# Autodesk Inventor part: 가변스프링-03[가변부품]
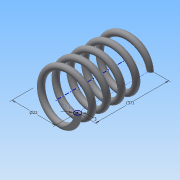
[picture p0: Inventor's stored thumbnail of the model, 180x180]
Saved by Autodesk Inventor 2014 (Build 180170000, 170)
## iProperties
Created: 2015-09
Part Number: 가변스프링-03[가변부품]
Material: 강철, 탄소
Document SubType Name: Modeling
Designer: study
Density: 7.87 g/cm^3
Appearance: 반연마
Mass: 18.8856 g
Surface Area: 32.5491 cm^2
Volume: 2.3997 cm^3
Author: study
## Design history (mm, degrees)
sketch "스케치1"
  geometry: L1 (0, 0)-(11, 0); L2 (11, 0)-(11, 36.411); L3 (11, 36.411)-(0, 36.411); L4 (0, 36.411)-(0, 0); C1 r 1.5 at (11, 0)
  constraints: 8 end point, 2 parallel, 1 centre point, 1 coincident, 1 horizontal, 1 perpendicular
  dimensions: "d0" = 22 diameter of L2 L4; "d1" = 36.4112 distance of L1.end L2.end (derived); "d2" = 3 diameter of C1
feature "코일1" sketch "스케치1" pitch "d3" = 10; turns "d5" = 5; dims "d4" = 36.4112 (= d1), "d6" = 0, angle "d7" = 90 deg, angle "d8" = 90 deg, "d9" = 0, "d10" = 0
sketch "스케치2"
  geometry: L1 (-12.5, 0)-(-9.5, 0) reference; L2 (-12.5, 0)-(-9.5, 0) reference; 1 further point
  constraints: 2 horizontal alignment
extrude "돌출1" cut sketch "스케치2" stored distance "d11" = 10; taper "d12" = 0 deg
node "작업 평면1"
sketch "스케치3"
  geometry: L1 (-9.5, 0)-(-12.5, 0) reference; 1 further point
  constraints: 1 horizontal alignment
extrude "돌출2" cut sketch "스케치3" stored distance "d14" = 10; taper "d15" = 0 deg
node "솔리드1"
node "절단 모서리 투영1"
node "절단 모서리 투영2"
node "절단 모서리 투영3"
other parameters: "d13" = 36.4112 (= d1)
